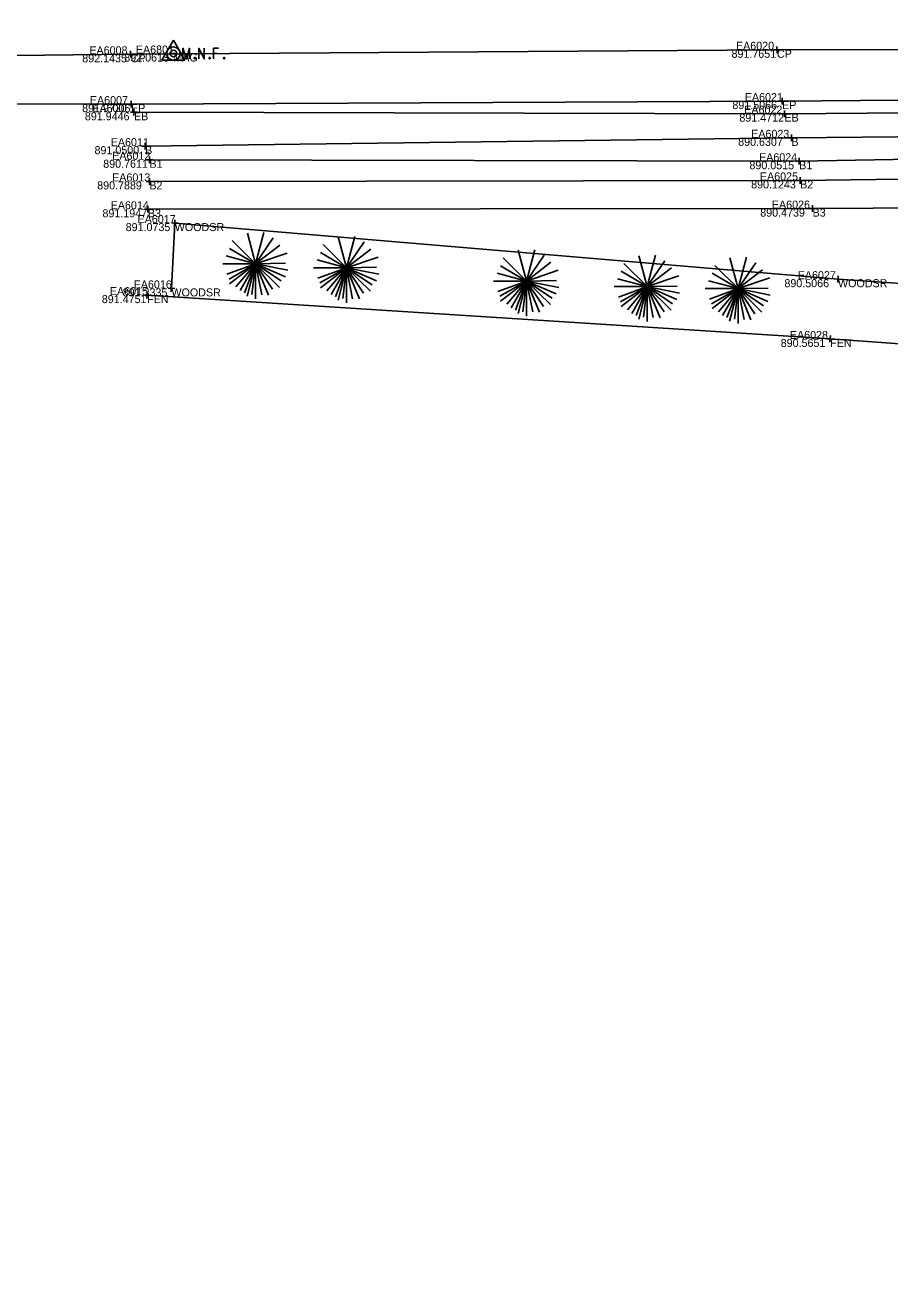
# Model space of a CAD drawing. Extents: x 179044 to 189691, y 286531 to 301257.
# Drawn here: x 179547.2 to 179676.8, y 300401.7 to 300591.3 of the extents above; entities that cross this region are included whole.
import ezdxf

# ---------------------------------------------------------------- set-up
doc = ezdxf.new("R2010")
doc.units = 0
for name, color, linetype in [('PV_X_COP', 7, 'Continuous'), ('PV_X_EOP', 7, 'Continuous'), ('PV_X_Shoulder_Aggregate', 7, 'Continuous'), ('RD_X_Fence', 7, 'Continuous'), ('SV_Control_Point', 7, 'Continuous'), ('SV_X_Break_Lines', 7, 'Continuous'), ('SV_X_Control_Cells_Found', 7, 'Continuous'), ('SV_X_Shot_Marker', 7, 'Continuous'), ('SV_X_Text_Comment', 7, 'Continuous'), ('SV_X_Text_Elevation', 7, 'Continuous'), ('SV_X_Text_Name', 7, 'Continuous'), ('VG_X_Cells', 7, 'Continuous'), ('VG_X_Text', 7, 'Continuous'), ('VG_X_Tree_Line_Lt', 7, 'Continuous')]:
    doc.layers.add(name, color=color, linetype=linetype)

msp = doc.modelspace()

# ---------------------------------------------------------------- linework, layer by layer
at = {"layer": 'PV_X_COP'}
msp.add_lwpolyline([(179370.61, 300584.89), (179476.83, 300585.94), (179562.95, 300586.92), (179659.85, 300587.6), (179771.17, 300587.77), (179881.15, 300588.6), (179985.73, 300588.17), (180079.83, 300588.61), (180147.69, 300589.87), (180172.03, 300590.64), (180187.46, 300591.9), (180203.62, 300593.32)], dxfattribs=at)
at = {"layer": 'PV_X_EOP'}
msp.add_lwpolyline([(179371.15, 300578.05), (179477.17, 300579.53), (179563.01, 300579.45), (179660.63, 300579.91), (179772.35, 300580.84), (179883.3, 300581.22), (179986.95, 300581.66), (180080.46, 300581.62), (180131.14, 300581.88), (180152.42, 300580.9), (180177.37, 300581.24), (180192.48, 300580.81), (180205.12, 300578.92), (180211.9, 300576.37), (180217.06, 300570.92), (180226.26, 300546.03), (180252.64, 300475.66), (180284.89, 300388.78), (180312.05, 300315.75), (180342, 300235.31)], dxfattribs=at)
at = {"layer": 'PV_X_Shoulder_Aggregate'}
msp.add_lwpolyline([(179563.45, 300578.23), (179660.98, 300578.02), (179772.75, 300578.9), (179883.7, 300579.45), (179986.9, 300579.72), (180080.26, 300579.65), (180131.52, 300579.63), (180152.89, 300578.4), (180177.17, 300578.87), (180192.85, 300577.82), (180203.73, 300575.4), (180212.87, 300569.27), (180224.05, 300544.43), (180250.42, 300474.5), (180282.67, 300386.99), (180309.92, 300313.99), (180339.84, 300234.33)], dxfattribs=at)
at = {"layer": 'RD_X_Fence'}
msp.add_lwpolyline([(179565.42, 300550.82), (179667.83, 300544.25), (179812.22, 300533.93), (179896.21, 300528.36), (179941.19, 300525.4), (180078.77, 300515.9), (180168.34, 300509.72), (180196.88, 300447.72), (180266.67, 300296.15), (180285.87, 300252.94)], dxfattribs=at)
at = {"layer": 'SV_Control_Point'}
for p, q in [((179567.63, 300586.04), (179569.36, 300589.04)), ((179569.36, 300589.04), (179571.09, 300586.04)), ((179571.09, 300586.04), (179567.63, 300586.04)), ((179569.36, 300587.04), (179569.36, 300587.04))]:
    msp.add_line(p, q, dxfattribs=at)
msp.add_circle((179569.36, 300587.04), 1, dxfattribs=at)
at = {"layer": 'SV_X_Break_Lines'}
for points in [[(179565.12, 300573.15), (179662.02, 300574.4), (179773.07, 300575.46), (179882.87, 300576.48), (179986.95, 300576.83), (180079.91, 300577.07), (180132.28, 300575.16), (180173.56, 300573.47), (180187.35, 300573.77), (180198.85, 300570.77)], [(179565.77, 300571.11), (179663.2, 300570.89), (179773.09, 300572.83), (179882.33, 300573.11), (179987.45, 300574.39), (180079.01, 300574.1), (180132.14, 300569.99), (180164.61, 300565.35), (180185.41, 300564.03)], [(179565.76, 300567.87), (179663.33, 300568.02), (179772.88, 300569.47), (179881.61, 300569.7), (179987.86, 300571.14), (180079.15, 300570.64), (180132.42, 300565.89), (180165.82, 300561.09), (180185.22, 300560.1)], [(180320.9, 300212.18), (180282.07, 300307.44), (180254.03, 300376.29), (180214.22, 300457.22), (180192.83, 300518.47), (180187, 300524.65), (180178.54, 300551.92), (180167.49, 300556.19), (180133.43, 300560.27), (180078.67, 300564.71), (179988.56, 300564.71), (179881.16, 300565.14), (179774.57, 300564.41), (179665.2, 300563.79), (179565.53, 300563.69)]]:
    msp.add_lwpolyline(points, dxfattribs=at)
at = {"layer": 'SV_X_Control_Cells_Found'}
for points in [[(179569.43, 300587), (179569.43, 300587.08), (179569.46, 300587), (179569.48, 300587.08), (179569.48, 300587)], [(179569.52, 300587.01), (179569.53, 300587.01), (179569.53, 300587.01), (179569.53, 300587), (179569.53, 300587), (179569.53, 300587), (179569.53, 300587), (179569.52, 300587), (179569.52, 300587), (179569.52, 300587), (179569.52, 300587), (179569.52, 300587.01), (179569.52, 300587.01)], [(179569.55, 300587), (179569.55, 300587.08), (179569.59, 300587), (179569.59, 300587.08)], [(179569.63, 300587.01), (179569.64, 300587.01), (179569.64, 300587.01), (179569.64, 300587), (179569.64, 300587), (179569.64, 300587), (179569.64, 300587), (179569.63, 300587), (179569.63, 300587), (179569.63, 300587), (179569.63, 300587), (179569.63, 300587.01), (179569.63, 300587.01)], [(179569.7, 300587.08), (179569.66, 300587.08), (179569.66, 300587)], [(179569.66, 300587.04), (179569.69, 300587.04)], [(179569.74, 300587.01), (179569.74, 300587.01), (179569.75, 300587.01), (179569.75, 300587), (179569.75, 300587), (179569.75, 300587), (179569.74, 300587), (179569.74, 300587), (179569.74, 300587), (179569.74, 300587), (179569.74, 300587), (179569.74, 300587.01), (179569.74, 300587.01)], [(179570.8, 300586.23), (179570.8, 300587.83), (179571.31, 300586.23), (179571.8, 300587.83), (179571.8, 300586.23)], [(179572.57, 300586.44), (179572.62, 300586.44), (179572.66, 300586.42), (179572.69, 300586.37), (179572.69, 300586.3), (179572.66, 300586.25), (179572.62, 300586.23), (179572.57, 300586.23), (179572.53, 300586.25), (179572.5, 300586.3), (179572.5, 300586.37), (179572.53, 300586.42), (179572.57, 300586.44)], [(179573.17, 300586.23), (179573.17, 300587.83), (179574, 300586.23), (179574, 300587.83)], [(179574.78, 300586.44), (179574.84, 300586.44), (179574.87, 300586.42), (179574.9, 300586.37), (179574.9, 300586.3), (179574.87, 300586.25), (179574.84, 300586.23), (179574.78, 300586.23), (179574.75, 300586.25), (179574.72, 300586.3), (179574.72, 300586.37), (179574.75, 300586.42), (179574.78, 300586.44)], [(179576.15, 300587.83), (179575.39, 300587.83), (179575.39, 300586.23)], [(179575.39, 300587.05), (179575.93, 300587.05)], [(179576.93, 300586.44), (179576.99, 300586.44), (179577.02, 300586.42), (179577.05, 300586.37), (179577.05, 300586.3), (179577.02, 300586.25), (179576.99, 300586.23), (179576.93, 300586.23), (179576.9, 300586.25), (179576.87, 300586.3), (179576.87, 300586.37), (179576.9, 300586.42), (179576.93, 300586.44)]]:
    msp.add_lwpolyline(points, dxfattribs=at)
for radius in [0.497, 0.0249]:
    msp.add_circle((179569.36, 300587.04), radius, dxfattribs=at)
at = {"layer": 'SV_X_Shot_Marker'}
for p, q in [((179659.85, 300588.1), (179659.86, 300587.1)), ((179562.45, 300586.91), (179563.45, 300586.93)), ((179562.94, 300587.42), (179562.96, 300586.42)), ((179562.95, 300586.92), (179562.95, 300586.92)), ((179659.35, 300587.6), (179660.35, 300587.61)), ((179659.85, 300587.6), (179659.85, 300587.6)), ((179660.62, 300580.41), (179660.63, 300579.41)), ((179562.51, 300579.46), (179563.51, 300579.45)), ((179563.01, 300579.95), (179563.01, 300578.95)), ((179563.01, 300579.45), (179563.01, 300579.45)), ((179563.45, 300578.73), (179563.45, 300577.73)), ((179660.13, 300579.9), (179661.13, 300579.91)), ((179660.63, 300579.91), (179660.63, 300579.91)), ((179660.98, 300578.52), (179660.98, 300577.52)), ((179562.95, 300578.23), (179563.95, 300578.23)), ((179563.45, 300578.23), (179563.45, 300578.23)), ((179660.48, 300578.02), (179661.48, 300578.01)), ((179660.98, 300578.02), (179660.98, 300578.02)), ((179662.02, 300574.9), (179662.03, 300573.9)), ((179564.62, 300573.14), (179565.62, 300573.16)), ((179565.11, 300573.65), (179565.12, 300572.65)), ((179565.12, 300573.15), (179565.12, 300573.15)), ((179661.52, 300574.39), (179662.52, 300574.4)), ((179662.02, 300574.4), (179662.02, 300574.4)), ((179565.27, 300571.11), (179566.27, 300571.11)), ((179565.77, 300571.61), (179565.76, 300570.61)), ((179565.77, 300571.11), (179565.77, 300571.11)), ((179662.7, 300570.89), (179663.7, 300570.89)), ((179663.2, 300571.39), (179663.2, 300570.39)), ((179663.2, 300570.89), (179663.2, 300570.89)), ((179565.26, 300567.87), (179566.26, 300567.87)), ((179565.76, 300568.37), (179565.76, 300567.37)), ((179565.76, 300567.87), (179565.76, 300567.87)), ((179662.83, 300568.02), (179663.83, 300568.02)), ((179663.33, 300568.52), (179663.34, 300567.52)), ((179663.33, 300568.02), (179663.33, 300568.02)), ((179566.03, 300563.69), (179565.03, 300563.69)), ((179565.53, 300563.19), (179565.53, 300564.19)), ((179565.53, 300563.69), (179565.53, 300563.69)), ((179665.7, 300563.79), (179664.7, 300563.79)), ((179665.2, 300563.29), (179665.2, 300564.29)), ((179665.2, 300563.79), (179665.2, 300563.79)), ((179569.07, 300561.64), (179570.07, 300561.59)), ((179569.55, 300561.12), (179569.6, 300562.12)), ((179569.57, 300561.62), (179569.57, 300561.62)), ((179568.57, 300551.85), (179569.57, 300551.8)), ((179569.04, 300551.33), (179569.09, 300552.33)), ((179668.51, 300553.25), (179669.51, 300553.16)), ((179669.05, 300553.7), (179668.97, 300552.71)), ((179669.01, 300553.21), (179669.01, 300553.21)), ((179564.93, 300550.86), (179565.92, 300550.79)), ((179565.46, 300551.32), (179565.39, 300550.32)), ((179565.42, 300550.82), (179565.42, 300550.82)), ((179569.07, 300551.83), (179569.07, 300551.83)), ((179667.33, 300544.28), (179668.33, 300544.22)), ((179667.86, 300544.75), (179667.8, 300543.75)), ((179667.83, 300544.25), (179667.83, 300544.25))]:
    msp.add_line(p, q, dxfattribs=at)
at = {"layer": 'VG_X_Cells'}
for p, q in [((179581.68, 300555.5), (179580.45, 300560.12)), ((179581.68, 300555.5), (179582.94, 300560.2)), ((179595.32, 300554.92), (179594.09, 300559.54)), ((179595.32, 300554.92), (179596.58, 300559.62)), ((179581.68, 300555.5), (179577.78, 300557.8)), ((179581.68, 300555.5), (179578.19, 300558.99)), ((179581.68, 300555.5), (179584.34, 300559.39)), ((179581.68, 300555.5), (179585.34, 300558.31)), ((179595.32, 300554.92), (179591.83, 300558.41)), ((179595.32, 300554.92), (179597.98, 300558.81)), ((179595.32, 300554.92), (179598.98, 300557.73)), ((179622.3, 300552.93), (179621.07, 300557.55)), ((179622.3, 300552.93), (179623.56, 300557.63)), ((179581.68, 300555.5), (179577.27, 300556.69)), ((179581.68, 300555.5), (179586.42, 300557.11)), ((179595.32, 300554.92), (179590.91, 300556.11)), ((179595.32, 300554.92), (179591.42, 300557.22)), ((179595.32, 300554.92), (179600.06, 300556.53)), ((179622.3, 300552.93), (179618.81, 300556.42)), ((179622.3, 300552.93), (179624.96, 300556.82)), ((179622.3, 300552.93), (179625.96, 300555.74)), ((179640.39, 300552.09), (179639.15, 300556.7)), ((179640.39, 300552.09), (179641.64, 300556.79)), ((179640.39, 300552.09), (179643.04, 300555.98)), ((179654.02, 300551.79), (179652.79, 300556.4)), ((179654.02, 300551.79), (179655.28, 300556.49)), ((179654.02, 300551.79), (179656.68, 300555.68)), ((179576.75, 300555.5), (179581.68, 300555.5)), ((179581.68, 300555.5), (179577.39, 300553.94)), ((179581.68, 300555.5), (179577.7, 300553.22)), ((179581.68, 300555.5), (179577.78, 300552.51)), ((179581.68, 300555.5), (179578.74, 300552.04)), ((179581.68, 300555.5), (179579.37, 300551.49)), ((179581.68, 300555.5), (179580.02, 300551.16)), ((179581.68, 300555.5), (179580.42, 300550.65)), ((179581.68, 300555.5), (179581.14, 300550.91)), ((179581.68, 300555.5), (179586.19, 300555.59)), ((179581.68, 300550.26), (179581.68, 300555.5)), ((179581.68, 300555.5), (179582.61, 300550.87)), ((179581.68, 300555.5), (179583.62, 300550.83)), ((179581.68, 300555.5), (179584.22, 300551.71)), ((179581.68, 300555.5), (179585.27, 300551.98)), ((179581.68, 300555.5), (179585.51, 300552.95)), ((179581.68, 300555.5), (179586.15, 300553.56)), ((179581.68, 300555.5), (179586.51, 300554.54)), ((179590.39, 300554.92), (179595.32, 300554.92)), ((179595.32, 300554.92), (179591.03, 300553.36)), ((179595.32, 300554.92), (179591.34, 300552.64)), ((179595.32, 300554.92), (179591.42, 300551.93)), ((179595.32, 300554.92), (179592.38, 300551.46)), ((179595.32, 300554.92), (179593, 300550.91)), ((179595.32, 300554.92), (179593.66, 300550.58)), ((179595.32, 300554.92), (179594.06, 300550.07)), ((179595.32, 300554.92), (179594.78, 300550.33)), ((179595.32, 300554.92), (179599.83, 300555.01)), ((179595.32, 300549.68), (179595.32, 300554.92)), ((179595.32, 300554.92), (179596.24, 300550.29)), ((179595.32, 300554.92), (179597.26, 300550.25)), ((179595.32, 300554.92), (179597.86, 300551.13)), ((179595.32, 300554.92), (179598.91, 300551.4)), ((179595.32, 300554.92), (179599.14, 300552.37)), ((179595.32, 300554.92), (179599.79, 300552.98)), ((179595.32, 300554.92), (179600.15, 300553.96)), ((179622.3, 300552.93), (179617.89, 300554.12)), ((179622.3, 300552.93), (179618.4, 300555.23)), ((179622.3, 300552.93), (179627.04, 300554.54)), ((179640.39, 300552.09), (179636.48, 300554.39)), ((179640.39, 300552.09), (179636.9, 300555.58)), ((179640.39, 300552.09), (179644.04, 300554.9)), ((179654.02, 300551.79), (179650.12, 300554.09)), ((179654.02, 300551.79), (179650.53, 300555.28)), ((179654.02, 300551.79), (179657.68, 300554.6)), ((179617.37, 300552.93), (179622.3, 300552.93)), ((179622.3, 300552.93), (179618.01, 300551.37)), ((179622.3, 300552.93), (179618.32, 300550.65)), ((179622.3, 300552.93), (179618.4, 300549.94)), ((179622.3, 300552.93), (179619.36, 300549.47)), ((179622.3, 300552.93), (179619.99, 300548.92)), ((179622.3, 300552.93), (179620.64, 300548.59)), ((179622.3, 300552.93), (179621.04, 300548.08)), ((179622.3, 300552.93), (179621.76, 300548.34)), ((179622.3, 300552.93), (179626.81, 300553.03)), ((179622.3, 300547.69), (179622.3, 300552.93)), ((179622.3, 300552.93), (179623.23, 300548.3)), ((179622.3, 300552.93), (179624.24, 300548.27)), ((179622.3, 300552.93), (179624.84, 300549.14)), ((179622.3, 300552.93), (179625.89, 300549.41)), ((179622.3, 300552.93), (179626.13, 300550.38)), ((179622.3, 300552.93), (179626.77, 300550.99)), ((179622.3, 300552.93), (179627.13, 300551.98)), ((179635.45, 300552.09), (179640.39, 300552.09)), ((179640.39, 300552.09), (179635.97, 300553.27)), ((179640.39, 300552.09), (179636.1, 300550.53)), ((179640.39, 300552.09), (179636.4, 300549.81)), ((179640.39, 300552.09), (179636.48, 300549.1)), ((179640.39, 300552.09), (179637.44, 300548.62)), ((179640.39, 300552.09), (179638.07, 300548.08)), ((179640.39, 300552.09), (179638.72, 300547.75)), ((179640.39, 300552.09), (179639.12, 300547.23)), ((179640.39, 300552.09), (179639.85, 300547.5)), ((179640.39, 300552.09), (179645.12, 300553.7)), ((179640.39, 300552.09), (179644.9, 300552.18)), ((179640.39, 300546.85), (179640.39, 300552.09)), ((179640.39, 300552.09), (179641.31, 300547.45)), ((179640.39, 300552.09), (179642.32, 300547.42)), ((179640.39, 300552.09), (179642.92, 300548.3)), ((179640.39, 300552.09), (179643.98, 300548.57)), ((179640.39, 300552.09), (179644.21, 300549.54)), ((179640.39, 300552.09), (179644.85, 300550.15)), ((179640.39, 300552.09), (179645.22, 300551.13)), ((179654.02, 300551.79), (179649.61, 300552.97)), ((179654.02, 300551.79), (179658.76, 300553.4)), ((179654.02, 300551.79), (179658.53, 300551.88)), ((179649.09, 300551.79), (179654.02, 300551.79)), ((179654.02, 300551.79), (179649.73, 300550.23)), ((179654.02, 300551.79), (179650.04, 300549.51)), ((179654.02, 300551.79), (179650.12, 300548.8)), ((179654.02, 300551.79), (179651.08, 300548.32)), ((179654.02, 300551.79), (179651.71, 300547.78)), ((179654.02, 300551.79), (179652.36, 300547.45)), ((179654.02, 300551.79), (179652.76, 300546.93)), ((179654.02, 300551.79), (179653.48, 300547.2)), ((179654.02, 300546.55), (179654.02, 300551.79)), ((179654.02, 300551.79), (179654.95, 300547.15)), ((179654.02, 300551.79), (179655.96, 300547.12)), ((179654.02, 300551.79), (179656.56, 300548)), ((179654.02, 300551.79), (179657.61, 300548.27)), ((179654.02, 300551.79), (179657.85, 300549.24)), ((179654.02, 300551.79), (179658.49, 300549.85)), ((179654.02, 300551.79), (179658.85, 300550.83))]:
    msp.add_line(p, q, dxfattribs=at)
at = {"layer": 'VG_X_Tree_Line_Lt'}
msp.add_lwpolyline([(179569.07, 300551.83), (179569.57, 300561.62), (179669.01, 300553.21), (179812.55, 300543.34), (179895.93, 300538.89), (179941.24, 300534.37), (180108.4, 300524.39), (180109.23, 300515)], dxfattribs=at)

# ---------------------------------------------------------------- texts
at = {"layer": 'SV_X_Text_Comment'}
for s, height, p in [('CP', 1.2, (179562.95, 300585.72)), ('MAG', 1.2, (179569.36, 300585.84)), ('CP', 1.2, (179659.85, 300586.4)), ('EP', 1.2, (179563.01, 300578.25)), ('EP', 1.2, (179660.63, 300578.71)), ('EB', 1.2, (179563.45, 300577.03)), ('EB', 1.2, (179660.98, 300576.82)), ('B', 1.2, (179565.12, 300571.95)), ('B', 1.2, (179662.02, 300573.2)), ('B1', 1.2, (179565.77, 300569.91)), ('B1', 1.2, (179663.2, 300569.69)), ('B2', 1.2, (179565.76, 300566.67)), ('B2', 1.2, (179663.33, 300566.82)), ('B3', 1.2, (179565.53, 300562.49)), ('B3', 1.2, (179665.2, 300562.59)), ('WOODSR', 1.2, (179569.57, 300560.42)), ('TE', 0.12, (179581.68, 300555.38)), ('TE', 0.12, (179595.32, 300554.8)), ('WOODSR', 1.2, (179569.07, 300550.63)), ('TE', 0.12, (179622.3, 300552.81)), ('TE', 0.12, (179640.39, 300551.97)), ('WOODSR', 1.2, (179669.01, 300552.01)), ('FEN', 1.2, (179565.42, 300549.62)), ('TE', 0.12, (179654.02, 300551.67)), ('FEN', 1.2, (179667.83, 300543.05))]:
    msp.add_text(s, height=height, dxfattribs=at).set_placement(p)
at = {"layer": 'SV_X_Text_Elevation'}
for s, height, p in [('892.1435', 1.2, (179555.7, 300585.72)), ('892.0613', 1.2, (179562, 300585.84)), ('892.06', 0.06, (179569.07, 300586.98)), ('891.7651', 1.2, (179653.04, 300586.4)), ('891.9720', 1.2, (179555.68, 300578.25)), ('891.5066', 1.2, (179653.17, 300578.71)), ('891.9446', 1.2, (179556.09, 300577.03)), ('891.4712', 1.2, (179654.22, 300576.82)), ('891.0500', 1.2, (179557.54, 300571.95)), ('890.6307', 1.2, (179654.04, 300573.2)), ('890.7611', 1.2, (179558.84, 300569.91)), ('890.0515', 1.2, (179655.73, 300569.69)), ('890.7889', 1.2, (179557.94, 300566.67)), ('890.1243', 1.2, (179655.98, 300566.82)), ('891.1947', 1.2, (179558.73, 300562.49)), ('890.4739', 1.2, (179657.35, 300562.59)), ('891.0735', 1.2, (179562.21, 300560.42)), ('890.9680', 0.06, (179581.29, 300555.44)), ('890.8040', 0.06, (179594.92, 300554.86)), ('891.3335', 1.2, (179561.77, 300550.63)), ('890.6800', 0.06, (179621.9, 300552.87)), ('890.5570', 0.06, (179639.99, 300552.03)), ('890.5066', 1.2, (179660.97, 300552.01)), ('891.4751', 1.2, (179558.63, 300549.62)), ('890.5960', 0.06, (179653.62, 300551.73)), ('890.5651', 1.2, (179660.42, 300543.05))]:
    msp.add_text(s, height=height, dxfattribs=at).set_placement(p)
at = {"layer": 'SV_X_Text_Name'}
for s, height, p in [('EA6008', 1.2, (179556.77, 300586.92)), ('EA6801', 1.2, (179563.74, 300587.04)), ('EA6020', 1.2, (179653.71, 300587.6)), ('EA6801', 0.06, (179569.08, 300587.04)), ('EA6007', 1.2, (179556.84, 300579.45)), ('EA6021', 1.2, (179655.03, 300579.91)), ('EA6006', 1.2, (179557.21, 300578.23)), ('EA6022', 1.2, (179654.95, 300578.02)), ('EA6023', 1.2, (179655.99, 300574.4)), ('EA6011', 1.2, (179559.97, 300573.15)), ('EA6012', 1.2, (179560.19, 300571.11)), ('EA6024', 1.2, (179657.17, 300570.89)), ('EA6013', 1.2, (179560.18, 300567.87)), ('EA6025', 1.2, (179657.3, 300568.02)), ('EA6014', 1.2, (179559.96, 300563.69)), ('EA6026', 1.2, (179659.09, 300563.79)), ('EA6017', 1.2, (179563.99, 300561.62)), ('SV5015', 0.06, (179581.41, 300555.5)), ('SV5016', 0.06, (179595.04, 300554.92)), ('EA6027', 1.2, (179662.97, 300553.21)), ('EA6015', 1.2, (179559.84, 300550.82)), ('EA6016', 1.2, (179563.41, 300551.83)), ('SV5017', 0.06, (179622.02, 300552.93)), ('SV5018', 0.06, (179640.11, 300552.09)), ('SV5019', 0.06, (179653.74, 300551.79)), ('EA6028', 1.2, (179661.79, 300544.25))]:
    msp.add_text(s, height=height, dxfattribs=at).set_placement(p)
at = {"layer": 'VG_X_Text'}
for s, p in [(' NOTE:8', (179581.68, 300555.5)), (' NOTE:6', (179595.32, 300554.92)), (' NOTE:8', (179622.3, 300552.93)), (' NOTE:6', (179640.39, 300552.09)), (' NOTE:6', (179654.02, 300551.79))]:
    msp.add_text(s, height=0.12, dxfattribs=at).set_placement(p)

doc.saveas('drawing.dxf')
